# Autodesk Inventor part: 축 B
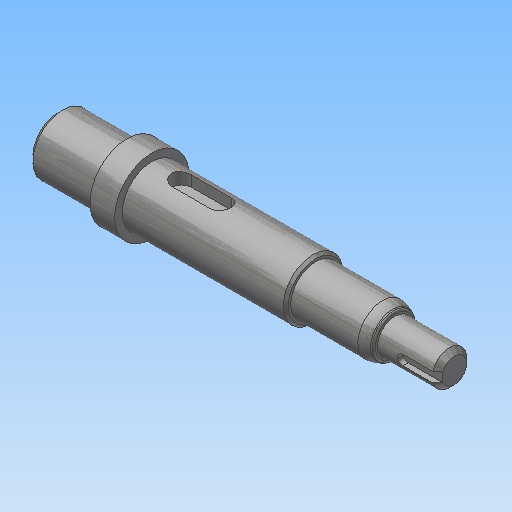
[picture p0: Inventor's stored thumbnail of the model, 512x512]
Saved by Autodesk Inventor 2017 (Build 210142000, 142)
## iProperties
Created: 2020-04
Part Number: 축 B
Material: 강철, 연강
Document SubType Name: Modeling
Designer: mduedu
Density: 7.86 g/cm^3
Appearance: 강철
Mass: 60.8547 g
Surface Area: 31.2855 cm^2
Volume: 7.74232 cm^3
Author: mduedu
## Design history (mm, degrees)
sketch "스케치1"
  geometry: L1 (0, 0)-(14, 0); L2 (14, 0)-(14, 6); L3 (14, 6)-(0, 6); L4 (0, 6)-(0, 0); L5 (14, 0)-(19, 0); L6 (19, 0)-(19, 7.5); L7 (19, 7.5)-(14, 7.5); L8 (14, 7.5)-(14, 0); L9 (19, 0)-(52, 0); L10 (52, 0)-(52, 6); L11 (52, 6)-(19, 6); L12 (19, 6)-(19, 0); L13 (52, 0)-(68, 0); L14 (68, 0)-(68, 5); L15 (68, 5)-(52, 5); L16 (52, 5)-(52, 0); L17 (68, 0)-(80, 0); L18 (80, 0)-(80, 3.5); L19 (80, 3.5)-(68, 3.5); L20 (68, 3.5)-(68, 0)
  constraints: 40 end point, 10 parallel, 5 horizontal, 5 perpendicular
  dimensions: "d0" = 80 distance between parallel lines of L18 L4; "d2" = 14 distance of L2.end L3.end; "d3" = 5 distance of L6.end L7.end; "d5" = 7 diameter of L19 L17; "d6" = 10 diameter of L15 L13; "d7" = 12 diameter of L11 L9; "d8" = 12 diameter of L3 L1; "d9" = 15 diameter of L7 L5; "d35" = 16 distance of L14.end L15.end; "d36" = 52 distance between parallel lines of L10 L4
revolve "회전1" sketch "스케치1" stored, may be unused: angle "d11" = 90 deg
sketch "스케치2"
  geometry: L1 (0, 6)-(0, -6) reference; L2 (0, -6)-(-14, -6) reference; L3 (-14, -6)-(-14, -7.5) reference; L4 (-14, -7.5)-(-19, -7.5) reference; L5 (-19, -7.5)-(-19, -6) reference; L6 (-19, -6)-(-52, -6) reference; L7 (-52, -6)-(-52, -5) reference; L8 (-52, -5)-(-68, -5) reference; L9 (-68, -5)-(-68, -3.5) reference; L10 (-68, -3.5)-(-80, -3.5) reference; L11 (-80, -3.5)-(-80, 3.5) reference; L12 (-80, 3.5)-(-68, 3.5) reference; L13 (-68, 3.5)-(-68, 5) reference; L14 (-68, 5)-(-52, 5) reference; L15 (-52, 5)-(-52, 6) reference; L16 (-52, 6)-(-19, 6) reference; L17 (-19, 6)-(-19, 7.5) reference; L18 (-19, 7.5)-(-14, 7.5) reference; L19 (-14, 7.5)-(-14, 6) reference; L20 (-14, 6)-(0, 6) reference; L21 (-80, 3.5)-(-72, 3.5); L22 (-72, 3.5)-(-72, 2.3); L23 (-72, 2.3)-(-80, 2.3); L24 (-80, 2.3)-(-80, 3.5); 1 further point
  constraints: 8 end point, 2 parallel, 1 horizontal, 1 perpendicular
  dimensions: "d37" = 8 distance of L22.end L23.end; "d38" = 1.2 distance of L21.end L22.end
extrude "돌출1" cut sketch "스케치2" stored distance "d14" = 2; taper "d15" = 0 deg
fillet "모깎기1" dims "d16" = 1
sketch "스케치3"
  geometry: L1 (0, -6)-(0, 6) reference; L2 (0, 6)-(14, 6) reference; L3 (14, 6)-(14, 7.5) reference; L4 (14, 7.5)-(19, 7.5) reference; L5 (19, 7.5)-(19, 6) reference; L6 (19, 6)-(52, 6) reference; L7 (52, 6)-(52, 5) reference; L8 (52, 5)-(68, 5) reference; L9 (68, 5)-(68, 3.5) reference; L10 (68, 3.5)-(80, 3.5) reference; L11 (80, 3.5)-(80, -3.5) reference; L12 (80, -3.5)-(68, -3.5) reference; L13 (68, -3.5)-(68, -5) reference; L14 (68, -5)-(52, -5) reference; L15 (52, -5)-(52, -6) reference; L16 (52, -6)-(19, -6) reference; L17 (19, -6)-(19, -7.5) reference; L18 (19, -7.5)-(14, -7.5) reference; L19 (14, -7.5)-(14, -6) reference; L20 (14, -6)-(0, -6) reference; L21 (23, 6)-(35, 6); L22 (35, 6)-(35, 3.5); L23 (35, 3.5)-(23, 3.5); L24 (23, 3.5)-(23, 6); 1 further point
  constraints: 8 end point, 2 parallel, 1 horizontal, 1 perpendicular, 1 point on line
  dimensions: "d17" = 12 distance of L22.end L23.end; "d18" = 2.5 distance of L21.end L22.end; "d19" = 4 distance from line of L24 L4.end
extrude "돌출2" cut sketch "스케치3" stored distance "d20" = 4; taper "d21" = 0 deg
fillet "모깎기2" dims "d22" = 2
chamfer "모따기1" distance "d23" = 1; stored, may be unused: second distance "d24" = 2, angle "d25" = 45 deg
chamfer "모따기2" distance "d26" = 0.5; stored, may be unused: second distance "d27" = 2, angle "d28" = 45 deg
fillet "모깎기3" dims "d29" = 0.3
chamfer "모따기3" distance "d30" = 1.39; stored, may be unused: second distance "d31" = 2, angle "d32" = 30 deg
fillet "모깎기4" dims "d33" = 4, "d34" = 0.5
node "솔리드1"
node "절단 모서리 투영2"
node "절단 모서리 투영3"
